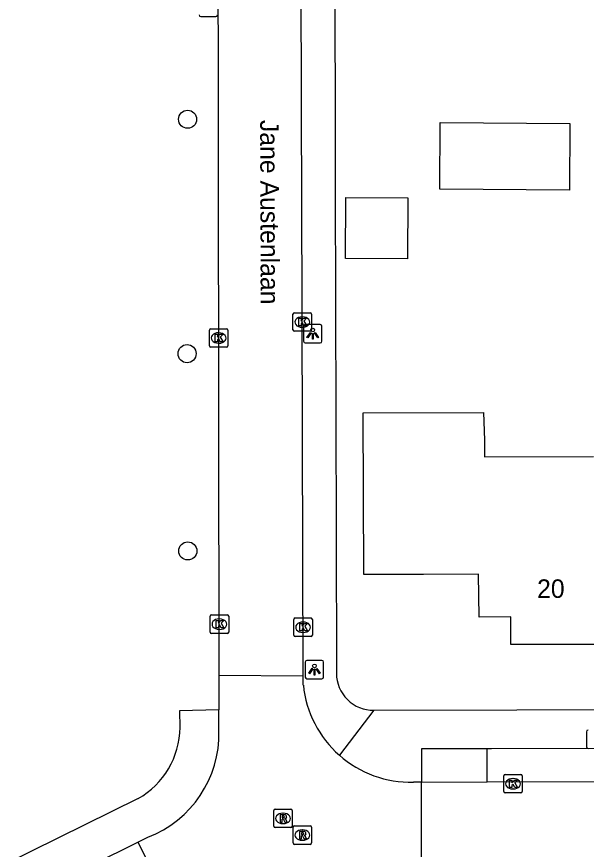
# Model space of a CAD drawing. Extents: x 160457 to 162082, y 388340 to 389736.
# Drawn here: x 160872.78 to 160903.56, y 388623.81 to 388668.76 of the extents above; entities that cross this region are included whole.
import ezdxf

# ---------------------------------------------------------------- set-up
doc = ezdxf.new("R2010")
doc.units = 0
for name, color, linetype in [('IMGEO_Boom', 7, 'Continuous'), ('IMGEO_Kolk', 7, 'Continuous'), ('IMGEO_Lichtpunt', 7, 'Continuous'), ('IMGEO_Muur', 7, 'Continuous'), ('IMGEO_Openbare_ruimte_label', 7, 'Continuous'), ('IMGEO_Pand', 7, 'Continuous'), ('IMGEO_Pand_nummerreeks', 7, 'Continuous'), ('IMGEO_Parkeervlak_open', 7, 'Continuous'), ('IMGEO_Rijbaan_lokaal_open', 7, 'Continuous'), ('IMGEO_Rioolput', 7, 'Continuous'), ('IMGEO_Voetpad_open', 7, 'Continuous')]:
    doc.layers.add(name, color=color, linetype=linetype)

msp = doc.modelspace()

# ---------------------------------------------------------------- linework, layer by layer
at = {"layer": 'IMGEO_Boom'}
for centre in [(160882.019, 388663.223), (160881.995, 388650.57), (160882.032, 388639.92)]:
    msp.add_circle(centre, 0.489, dxfattribs=at)
at = {"layer": 'IMGEO_Kolk'}
for p, q in [((160887.714, 388651.851), (160887.714, 388652.703)), ((160887.789, 388652.777), (160888.641, 388652.777)), ((160888.202, 388652.557), (160888.227, 388652.557)), ((160888.715, 388652.703), (160888.715, 388651.851)), ((160883.196, 388650.989), (160883.196, 388651.841)), ((160883.271, 388651.915), (160884.123, 388651.915)), ((160883.684, 388651.695), (160883.709, 388651.695)), ((160884.197, 388651.841), (160884.197, 388650.989)), ((160888.641, 388651.777), (160887.789, 388651.777)), ((160888.225, 388651.997), (160888.2, 388651.997)), ((160884.123, 388650.915), (160883.271, 388650.915)), ((160883.707, 388651.135), (160883.682, 388651.135)), ((160883.239, 388635.541), (160883.239, 388636.393)), ((160883.314, 388636.467), (160884.166, 388636.467)), ((160884.24, 388636.393), (160884.24, 388635.541)), ((160883.727, 388636.247), (160883.752, 388636.247)), ((160887.761, 388635.375), (160887.761, 388636.227)), ((160887.836, 388636.301), (160888.688, 388636.301)), ((160888.249, 388636.081), (160888.274, 388636.081)), ((160888.762, 388636.227), (160888.762, 388635.375)), ((160883.75, 388635.687), (160883.725, 388635.687)), ((160888.272, 388635.521), (160888.247, 388635.521)), ((160884.166, 388635.467), (160883.314, 388635.467)), ((160888.688, 388635.301), (160887.836, 388635.301)), ((160899.174, 388627.854), (160900.026, 388627.854)), ((160899.099, 388626.928), (160899.099, 388627.78)), ((160899.587, 388627.634), (160899.612, 388627.634)), ((160900.1, 388627.78), (160900.1, 388626.928)), ((160899.61, 388627.074), (160899.585, 388627.074)), ((160900.026, 388626.854), (160899.174, 388626.854))]:
    msp.add_line(p, q, dxfattribs=at)
for points in [[(160887.714, 388651.851), (160887.714, 388652.703)], [(160887.789, 388652.777), (160888.641, 388652.777)], [(160888.715, 388652.703), (160888.715, 388651.851)], [(160888.035, 388652.477), (160888.158, 388652.477), (160888.158, 388652.326), (160888.288, 388652.477), (160888.452, 388652.477), (160888.306, 388652.326), (160888.459, 388652.077), (160888.307, 388652.077), (160888.222, 388652.241), (160888.158, 388652.174), (160888.158, 388652.077), (160888.035, 388652.077), (160888.035, 388652.477)], [(160883.196, 388650.989), (160883.196, 388651.841)], [(160883.271, 388651.915), (160884.123, 388651.915)], [(160884.197, 388651.841), (160884.197, 388650.989)], [(160888.641, 388651.777), (160887.789, 388651.777)], [(160883.517, 388651.615), (160883.64, 388651.615), (160883.64, 388651.464), (160883.77, 388651.615), (160883.934, 388651.615), (160883.788, 388651.464), (160883.941, 388651.215), (160883.789, 388651.215), (160883.704, 388651.379), (160883.64, 388651.312), (160883.64, 388651.215), (160883.517, 388651.215), (160883.517, 388651.615)], [(160884.123, 388650.915), (160883.271, 388650.915)], [(160883.239, 388635.541), (160883.239, 388636.393)], [(160883.314, 388636.467), (160884.166, 388636.467)], [(160884.24, 388636.393), (160884.24, 388635.541)], [(160883.56, 388636.167), (160883.683, 388636.167), (160883.683, 388636.016), (160883.813, 388636.167), (160883.977, 388636.167), (160883.831, 388636.016), (160883.984, 388635.767), (160883.832, 388635.767), (160883.747, 388635.931), (160883.683, 388635.864), (160883.683, 388635.767), (160883.56, 388635.767), (160883.56, 388636.167)], [(160887.761, 388635.375), (160887.761, 388636.227)], [(160887.836, 388636.301), (160888.688, 388636.301)], [(160888.082, 388636.001), (160888.205, 388636.001), (160888.205, 388635.85), (160888.335, 388636.001), (160888.499, 388636.001), (160888.353, 388635.85), (160888.506, 388635.601), (160888.354, 388635.601), (160888.269, 388635.765), (160888.205, 388635.698), (160888.205, 388635.601), (160888.082, 388635.601), (160888.082, 388636.001)], [(160888.762, 388636.227), (160888.762, 388635.375)], [(160884.166, 388635.467), (160883.314, 388635.467)], [(160888.688, 388635.301), (160887.836, 388635.301)], [(160899.174, 388627.854), (160900.026, 388627.854)], [(160899.099, 388626.928), (160899.099, 388627.78)], [(160899.42, 388627.554), (160899.543, 388627.554), (160899.543, 388627.403), (160899.673, 388627.554), (160899.837, 388627.554), (160899.691, 388627.403), (160899.844, 388627.154), (160899.692, 388627.154), (160899.607, 388627.318), (160899.543, 388627.251), (160899.543, 388627.154), (160899.42, 388627.154), (160899.42, 388627.554)], [(160900.1, 388627.78), (160900.1, 388626.928)], [(160900.026, 388626.854), (160899.174, 388626.854)]]:
    msp.add_lwpolyline(points, dxfattribs=at)
for centre, start, end in [((160887.791, 388652.701), 91.552, 178.448), ((160887.791, 388652.701), 91.552, 178.448), ((160888.639, 388652.701), 1.552, 88.448), ((160888.639, 388652.701), 1.552, 88.448), ((160883.273, 388651.839), 91.552, 178.448), ((160883.273, 388651.839), 91.552, 178.448), ((160884.121, 388651.839), 1.552, 88.448), ((160884.121, 388651.839), 1.552, 88.448), ((160887.791, 388651.853), 181.552, 268.448), ((160887.791, 388651.853), 181.552, 268.448), ((160888.639, 388651.853), 271.552, 358.448), ((160888.639, 388651.853), 271.552, 358.448), ((160883.273, 388650.991), 181.552, 268.448), ((160883.273, 388650.991), 181.552, 268.448), ((160884.121, 388650.991), 271.552, 358.448), ((160884.121, 388650.991), 271.552, 358.448), ((160883.316, 388636.391), 91.552, 178.448), ((160883.316, 388636.391), 91.552, 178.448), ((160884.164, 388636.391), 1.552, 88.448), ((160884.164, 388636.391), 1.552, 88.448), ((160887.838, 388636.225), 91.552, 178.448), ((160887.838, 388636.225), 91.552, 178.448), ((160888.686, 388636.225), 1.552, 88.448), ((160888.686, 388636.225), 1.552, 88.448), ((160883.316, 388635.543), 181.552, 268.448), ((160883.316, 388635.543), 181.552, 268.448), ((160884.164, 388635.543), 271.552, 358.448), ((160884.164, 388635.543), 271.552, 358.448), ((160887.838, 388635.377), 181.552, 268.448), ((160887.838, 388635.377), 181.552, 268.448), ((160888.686, 388635.377), 271.552, 358.448), ((160888.686, 388635.377), 271.552, 358.448), ((160899.176, 388627.778), 91.552, 178.448), ((160899.176, 388627.778), 91.552, 178.448), ((160900.024, 388627.778), 1.552, 88.448), ((160900.024, 388627.778), 1.552, 88.448), ((160899.176, 388626.93), 181.552, 268.448), ((160899.176, 388626.93), 181.552, 268.448), ((160900.024, 388626.93), 271.552, 358.448), ((160900.024, 388626.93), 271.552, 358.448)]:
    msp.add_arc(centre, 0.0765, start, end, dxfattribs=at)
for centre, major_axis, ratio, start_param, end_param in [((160888.201, 388652.277), (-0.387, 0.002), 0.722429, 4.712389, 7.853982), ((160888.226, 388652.277), (-0.39, 0.002), 0.717154, 1.570796, 4.712389), ((160883.683, 388651.415), (-0.387, 0.002), 0.722429, 4.712389, 7.853982), ((160883.708, 388651.415), (-0.39, 0.002), 0.717154, 1.570796, 4.712389), ((160883.726, 388635.967), (-0.387, 0.002), 0.722429, 4.712389, 7.853982), ((160883.751, 388635.967), (-0.39, 0.002), 0.717154, 1.570796, 4.712389), ((160888.248, 388635.801), (-0.387, 0.002), 0.722429, 4.712389, 7.853982), ((160888.273, 388635.801), (-0.39, 0.002), 0.717154, 1.570796, 4.712389), ((160899.586, 388627.354), (-0.387, 0.002), 0.722429, 4.712389, 7.853982), ((160899.611, 388627.354), (-0.39, 0.002), 0.717154, 1.570796, 4.712389)]:
    msp.add_ellipse(centre, major_axis=major_axis, ratio=ratio, start_param=start_param, end_param=end_param, dxfattribs=at)
at = {"layer": 'IMGEO_Lichtpunt'}
for p, q in [((160882.732, 388668.763), (160883.54, 388668.763)), ((160882.732, 388668.763), (160883.54, 388668.763)), ((160889.186, 388652.145), (160888.378, 388652.145)), ((160889.186, 388652.145), (160888.378, 388652.145)), ((160888.284, 388652.05), (160888.284, 388651.243)), ((160888.284, 388652.05), (160888.284, 388651.243)), ((160889.28, 388651.243), (160889.28, 388652.05)), ((160889.28, 388651.243), (160889.28, 388652.05)), ((160888.378, 388651.149), (160889.186, 388651.149)), ((160888.378, 388651.149), (160889.186, 388651.149)), ((160888.375, 388633.919), (160888.375, 388633.112)), ((160888.375, 388633.919), (160888.375, 388633.112)), ((160889.277, 388634.014), (160888.469, 388634.014)), ((160889.277, 388634.014), (160888.469, 388634.014)), ((160889.371, 388633.112), (160889.371, 388633.919)), ((160889.371, 388633.112), (160889.371, 388633.919)), ((160888.469, 388633.018), (160889.277, 388633.018)), ((160888.469, 388633.018), (160889.277, 388633.018)), ((160903.564, 388630.157), (160903.564, 388629.35)), ((160903.564, 388630.157), (160903.564, 388629.35))]:
    msp.add_line(p, q, dxfattribs=at)
for points in [[(160888.658, 388651.714), (160888.697, 388651.686), (160888.509, 388651.424), (160888.471, 388651.451), (160888.658, 388651.714)], [(160888.76, 388651.666), (160888.807, 388651.666), (160888.807, 388651.344), (160888.76, 388651.344), (160888.76, 388651.666)], [(160888.87, 388651.686), (160888.908, 388651.713), (160889.095, 388651.451), (160889.056, 388651.423), (160888.87, 388651.686)], [(160888.749, 388633.583), (160888.788, 388633.555), (160888.6, 388633.293), (160888.562, 388633.32), (160888.749, 388633.583)], [(160888.851, 388633.535), (160888.898, 388633.535), (160888.898, 388633.213), (160888.851, 388633.213), (160888.851, 388633.535)], [(160888.961, 388633.555), (160888.999, 388633.582), (160889.186, 388633.32), (160889.147, 388633.292), (160888.961, 388633.555)]]:
    msp.add_lwpolyline(points, dxfattribs=at)
for centre in [(160888.783, 388651.848), (160888.874, 388633.717)]:
    msp.add_circle(centre, 0.0994, dxfattribs=at)
for centre, start, end in [((160882.732, 388668.857), 180, 270), ((160882.732, 388668.857), 180, 270), ((160883.54, 388668.857), 270, 0), ((160883.54, 388668.857), 270, 360), ((160888.378, 388652.05), 90, 180), ((160888.378, 388652.05), 90, 180), ((160889.186, 388652.05), 0, 90), ((160889.186, 388652.05), 0, 90), ((160888.378, 388651.243), 180, 270), ((160888.378, 388651.243), 180, 270), ((160889.186, 388651.243), 270, 0), ((160889.186, 388651.243), 270, 360), ((160888.469, 388633.919), 90, 180), ((160888.469, 388633.919), 90, 180), ((160889.277, 388633.919), 0, 90), ((160889.277, 388633.919), 0, 90), ((160888.469, 388633.112), 180, 270), ((160888.469, 388633.112), 180, 270), ((160889.277, 388633.112), 270, 0), ((160889.277, 388633.112), 270, 360), ((160903.658, 388630.157), 90, 180), ((160903.658, 388630.157), 90, 180), ((160903.658, 388629.35), 180, 270), ((160903.658, 388629.35), 180, 270)]:
    msp.add_arc(centre, 0.0946, start, end, dxfattribs=at)
at = {"layer": 'IMGEO_Muur'}
for points in [[(160889.963, 388675.844), (160889.993, 388663.094)], [(160890.002, 388659.496), (160890.046, 388640.927)]]:
    msp.add_lwpolyline(points, dxfattribs=at)
at = {"layer": 'IMGEO_Pand'}
for points in [[(160902.649, 388659.397), (160895.641, 388659.452), (160895.666, 388663.05), (160902.676, 388662.996), (160902.649, 388659.397)], [(160893.892, 388655.69), (160890.549, 388655.713), (160890.571, 388659.007), (160893.915, 388658.984), (160893.892, 388655.69)], [(160903.991, 388634.867), (160899.482, 388634.862), (160899.482, 388636.358), (160897.77, 388636.351), (160897.739, 388638.667), (160894.761, 388638.657), (160891.541, 388638.646), (160891.512, 388647.372), (160898.002, 388647.394), (160898.058, 388645.899), (160898.061, 388645), (160903.941, 388645.02)]]:
    msp.add_lwpolyline(points, dxfattribs=at)
at = {"layer": 'IMGEO_Parkeervlak_open'}
msp.add_lwpolyline([(160898.208, 388627.447), (160898.203, 388629.235)], dxfattribs=at)
at = {"layer": 'IMGEO_Rijbaan_lokaal_open'}
for points in [[(160883.632, 388689.418), (160883.703, 388633.217)], [(160888.272, 388633.182), (160888.197, 388659.163), (160888.173, 388663.388), (160888.127, 388687.282)], [(160883.703, 388633.217), (160888.272, 388633.182)], [(160883.703, 388633.217), (160883.705, 388631.337)], [(160888.273, 388632.674), (160888.272, 388633.182)], [(160883.716, 388630.19), (160883.705, 388631.337)], [(160894.661, 388627.437), (160894.22, 388627.439)], [(160894.661, 388627.437), (160898.208, 388627.447)], [(160894.662, 388622.666), (160894.661, 388627.437)], [(160898.208, 388627.447), (160909.903, 388627.48)], [(160879.337, 388624.202), (160879.879, 388624.47)], [(160866.632, 388618.016), (160867.306, 388618.248), (160879.337, 388624.202)], [(160879.337, 388624.202), (160881.408, 388620.152), (160881.468, 388620.03)]]:
    msp.add_lwpolyline(points, dxfattribs=at)
for centre, radius, start, end in [((160894.067, 388633.26), 5.823, 185.7749, 228.6436), ((160877.745, 388630.048), 5.972, 290.9327, 1.3595), ((160894.064, 388633.254), 5.817, 228.621, 271.537)]:
    msp.add_arc(centre, radius, start, end, dxfattribs=at)
at = {"layer": 'IMGEO_Rioolput'}
for p, q in [((160886.677, 388625.056), (160886.677, 388625.908)), ((160886.752, 388625.982), (160887.604, 388625.982)), ((160887.165, 388625.762), (160887.19, 388625.762)), ((160887.678, 388625.908), (160887.678, 388625.056)), ((160887.188, 388625.202), (160887.163, 388625.202)), ((160887.604, 388624.982), (160886.752, 388624.982)), ((160887.721, 388624.154), (160887.721, 388625.006)), ((160887.796, 388625.08), (160888.648, 388625.08)), ((160888.209, 388624.86), (160888.234, 388624.86)), ((160888.722, 388625.006), (160888.722, 388624.154)), ((160888.232, 388624.3), (160888.207, 388624.3)), ((160888.648, 388624.08), (160887.796, 388624.08))]:
    msp.add_line(p, q, dxfattribs=at)
for points in [[(160886.677, 388625.056), (160886.677, 388625.908)], [(160886.752, 388625.982), (160887.604, 388625.982)], [(160887.266, 388625.68), (160887.014, 388625.682), (160887.014, 388625.282)], [(160887.192, 388625.601), (160887.138, 388625.601), (160887.138, 388625.52)], [(160887.678, 388625.908), (160887.678, 388625.056)], [(160887.014, 388625.282), (160887.138, 388625.282), (160887.138, 388625.444), (160887.149, 388625.444)], [(160887.138, 388625.52), (160887.19, 388625.52)], [(160887.196, 388625.415), (160887.267, 388625.282), (160887.407, 388625.282), (160887.342, 388625.408)], [(160887.604, 388624.982), (160886.752, 388624.982)], [(160887.721, 388624.154), (160887.721, 388625.006)], [(160887.796, 388625.08), (160888.648, 388625.08)], [(160888.31, 388624.778), (160888.058, 388624.78), (160888.058, 388624.38)], [(160888.236, 388624.699), (160888.182, 388624.699), (160888.182, 388624.618)], [(160888.722, 388625.006), (160888.722, 388624.154)], [(160888.058, 388624.38), (160888.182, 388624.38), (160888.182, 388624.542), (160888.193, 388624.542)], [(160888.182, 388624.618), (160888.234, 388624.618)], [(160888.24, 388624.513), (160888.311, 388624.38), (160888.451, 388624.38), (160888.386, 388624.506)], [(160888.648, 388624.08), (160887.796, 388624.08)]]:
    msp.add_lwpolyline(points, dxfattribs=at)
for centre, radius, start, end in [((160886.754, 388625.906), 0.0765, 91.552, 178.448), ((160886.754, 388625.906), 0.0765, 91.552, 178.448), ((160887.198, 388625.505), 0.0964, 77.0061, 93.1865), ((160887.212, 388625.562), 0.0378, 276.6634, 79.6772), ((160887.265, 388625.57), 0.109, 350.3612, 89.416), ((160887.602, 388625.906), 0.0765, 1.552, 88.448), ((160887.602, 388625.906), 0.0765, 1.552, 88.448), ((160887.148, 388625.391), 0.0533, 26.0293, 88.6989), ((160887.174, 388625.709), 0.19, 274.7715, 282.9687), ((160887.263, 388625.57), 0.112, 277.5842, 350.9817), ((160887.247, 388625.355), 0.108, 29.5134, 73.7905), ((160886.754, 388625.058), 0.0765, 181.552, 268.448), ((160886.754, 388625.058), 0.0765, 181.552, 268.448), ((160887.602, 388625.058), 0.0765, 271.552, 358.448), ((160887.602, 388625.058), 0.0765, 271.552, 358.448), ((160887.798, 388625.004), 0.0765, 91.552, 178.448), ((160887.798, 388625.004), 0.0765, 91.552, 178.448), ((160888.242, 388624.603), 0.0964, 77.0061, 93.1865), ((160888.256, 388624.66), 0.0378, 276.6634, 79.6772), ((160888.309, 388624.668), 0.109, 350.3612, 89.416), ((160888.646, 388625.004), 0.0765, 1.552, 88.448), ((160888.646, 388625.004), 0.0765, 1.552, 88.448), ((160888.192, 388624.489), 0.0533, 26.0293, 88.6989), ((160888.218, 388624.807), 0.19, 274.7715, 282.9687), ((160888.307, 388624.668), 0.112, 277.5842, 350.9817), ((160888.291, 388624.453), 0.108, 29.5134, 73.7905), ((160887.798, 388624.156), 0.0765, 181.552, 268.448), ((160887.798, 388624.156), 0.0765, 181.552, 268.448), ((160888.646, 388624.156), 0.0765, 271.552, 358.448), ((160888.646, 388624.156), 0.0765, 271.552, 358.448)]:
    msp.add_arc(centre, radius, start, end, dxfattribs=at)
for centre, major_axis, ratio, start_param, end_param in [((160887.164, 388625.482), (-0.387, 0.002), 0.722429, 4.712389, 7.853982), ((160887.189, 388625.482), (-0.39, 0.002), 0.717154, 1.570796, 4.712389), ((160888.208, 388624.58), (-0.387, 0.002), 0.722429, 4.712389, 7.853982), ((160888.233, 388624.58), (-0.39, 0.002), 0.717154, 1.570796, 4.712389)]:
    msp.add_ellipse(centre, major_axis=major_axis, ratio=ratio, start_param=start_param, end_param=end_param, dxfattribs=at)
at = {"layer": 'IMGEO_Voetpad_open'}
for points in [[(160889.936, 388687.264), (160889.963, 388675.844), (160889.993, 388663.094), (160890.002, 388659.496), (160890.046, 388640.927), (160890.064, 388633.311)], [(160892.083, 388631.326), (160946.205, 388631.457), (160987.335, 388631.563), (160996.857, 388631.585)], [(160883.705, 388631.337), (160881.576, 388631.282), (160881.61, 388630.39)], [(160892.083, 388631.326), (160890.219, 388628.889)], [(160898.203, 388629.235), (160894.663, 388629.231), (160894.661, 388627.437)], [(160909.898, 388629.266), (160909.644, 388629.266), (160898.435, 388629.235), (160898.203, 388629.235)], [(160879.343, 388626.548), (160866.349, 388620.152)]]:
    msp.add_lwpolyline(points, dxfattribs=at)
for centre, radius, start, end in [((160892.045, 388633.306), 1.981, 179.8653, 271.1077), ((160877.146, 388630.434), 4.465, 299.484, 359.4299)]:
    msp.add_arc(centre, radius, start, end, dxfattribs=at)

# ---------------------------------------------------------------- texts
at = {"layer": 'IMGEO_Openbare_ruimte_label'}
msp.add_text('Jane Austenlaan', height=1, rotation=270.1719, dxfattribs=at).set_placement((160885.94, 388663.187))
at = {"layer": 'IMGEO_Pand_nummerreeks'}
msp.add_text('20', height=1, rotation=0.0637, dxfattribs=at).set_placement((160900.903, 388637.383))

doc.saveas('drawing.dxf')
